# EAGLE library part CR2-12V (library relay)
DUAL POWER QUIET AUTOMOTIVE RELAY NAiS Source: http://www.mew-europe.com/.. en_ds_61209_0000.pdf
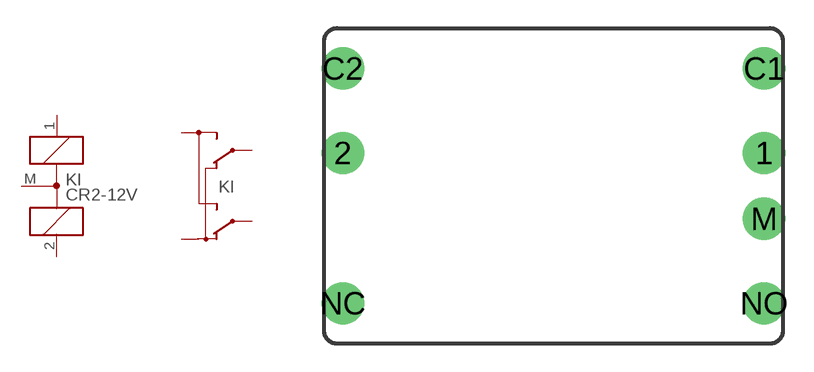
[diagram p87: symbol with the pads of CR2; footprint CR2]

Designator prefix KI; gates 1=K2-1 2=CF

## CR2-12V (MF: AROMAT/ MATSUSHITA; MPN: CR2-12V; OC_FARNELL: unknown; OC_NEWARK: 10C5511)  [CR2]
1  1:1  pas
2  1:2  pas
C1  2:COM1  pas
C2  2:COM2  pas
M  1:M  pas
NC  2:NC  pas
NO  2:NO  pas

## Footprint CR2 (pad centres in mm)
DUAL POWER QUIET AUTOMOTIVE RELAY NAiS Source: http://www.mew-europe.com/.. en_ds_61209_0000.pdf
drill 1.5 round: 1 11.2,1.75; 2 -11.2,1.75; C1 11.2,6.25; C2 -11.2,6.25; M 11.2,-1.75; NC -11.2,-6.25; NO 11.2,-6.25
